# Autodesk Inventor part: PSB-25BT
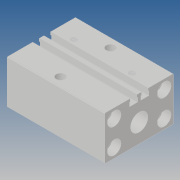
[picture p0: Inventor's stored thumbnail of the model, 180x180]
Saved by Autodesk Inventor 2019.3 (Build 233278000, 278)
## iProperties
Created: 2010-02
Part Number: PSB-25BT
Material: Ogólny
Document SubType Name: Modeling
Designer: CADENGINEERING4
Density: 1 g/cm^3
Appearance: Domyślna
Author: CADENGINEERING4
Revision Number: 1LAST_VERSION
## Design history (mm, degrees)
feature "Baza1"
sketch "Szkic2"
  geometry: C1 r 3.4 at (7.5, 27) reference; C2 r 3.4 at (7.5, 7) reference; C3 r 3.4 at (47.5, 7) reference; C4 r 3.4 at (47.5, 27) reference; C5 r 5.5 at (7.5, 7) reference; C6 r 5.5 at (7.5, 27) reference; C7 r 5.5 at (47.5, 27) reference; C8 r 5.5 at (47.5, 7) reference; 1 further point
sketch "Szkic3"
  geometry: L1 (13.261, 32.953)-(0.769, 32.953); L2 (0.769, 32.953)-(0.769, 0.723); L3 (0.769, 0.723)-(13.261, 0.723); L4 (13.261, 0.723)-(13.261, 32.953); L5 (54.069, 32.953)-(40.827, 32.953); L6 (40.827, 32.953)-(40.827, 0.723); L7 (40.827, 0.723)-(54.069, 0.723); L8 (54.069, 0.723)-(54.069, 32.953); 1 further point
  constraints: 16 end point, 4 parallel, 2 horizontal, 2 perpendicular, 2 point on line
extrude "Wyciągnięcie proste1" join sketch "Szkic3" distance "d0" = 20; taper "d1" = 0 deg
hole "Otwór1" sketch "Szkic2" diameter "d2" = 6.647; stored, may be unused: countersink angle "d6" = 90 deg, drill point angle "d8" = 118 deg; dims "d3" = 20, "d4" = 4, "d5" = 2, "d7" = 22.2
node "Bryła1"
